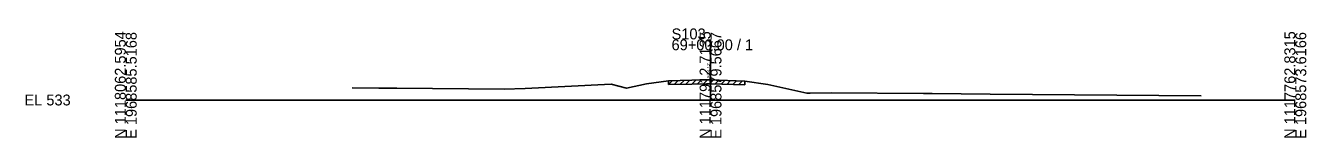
# Model space of a CAD drawing. Extents: x 974 to 1303, y 990 to 14518.
# Drawn here: x 974.3 to 1302.8, y 10990.3 to 11018.4 of the extents above; entities that cross this region are included whole.
import ezdxf

# ---------------------------------------------------------------- set-up
doc = ezdxf.new("R2010")
doc.units = 0
for name, color, linetype in [('Level 10', 7, 'Continuous'), ('Level 60', 7, 'Continuous'), ('Level 61', 7, 'Continuous'), ('Level 63', 7, 'Continuous')]:
    doc.layers.add(name, color=color, linetype=linetype)

msp = doc.modelspace()

# ---------------------------------------------------------------- linework, layer by layer
at = {"layer": 'Level 60'}
for p, q in [((1058.09, 11003.1), (1064.92, 11003.07)), ((1064.92, 11003.07), (1069.53, 11003.06)), ((1069.53, 11003.06), (1097.05, 11002.78)), ((1097.05, 11002.78), (1102.49, 11003)), ((1102.49, 11003), (1124.5, 11004.04)), ((1124.5, 11004.04), (1128.45, 11003.02)), ((1128.45, 11003.02), (1133.58, 11004.2)), ((1133.58, 11004.2), (1139.19, 11004.97)), ((1139.19, 11004.97), (1145.2, 11005.11)), ((1145.2, 11005.11), (1148.99, 11005.2)), ((1148.99, 11005.2), (1150, 11005.17)), ((1150, 11005.17), (1158.78, 11004.87)), ((1158.78, 11004.87), (1164.7, 11004.01)), ((1164.7, 11004.01), (1174.7, 11001.72)), ((1174.7, 11001.72), (1175.58, 11001.74)), ((1175.58, 11001.74), (1180.91, 11001.86)), ((1180.91, 11001.86), (1204.62, 11001.67)), ((1204.62, 11001.67), (1206.81, 11001.66)), ((1206.81, 11001.66), (1221.72, 11001.51)), ((1221.72, 11001.51), (1275.87, 11001.06))]:
    msp.add_line(p, q, dxfattribs=at)
at = {"layer": 'Level 61'}
for p, q in [((1139.19, 11003.97), (1140.21, 11004.99)), ((1139.19, 11003.97), (1139.19, 11004.97)), ((1139.19, 11003.97), (1145.2, 11004.11)), ((1140.69, 11004), (1141.71, 11005.03)), ((1142.19, 11004.04), (1143.21, 11005.06)), ((1143.69, 11004.07), (1144.71, 11005.1)), ((1145.19, 11004.11), (1146.21, 11005.13)), ((1145.2, 11004.11), (1148.99, 11004.2)), ((1146.69, 11004.14), (1147.71, 11005.17)), ((1148.19, 11004.18), (1149.2, 11005.19)), ((1148.99, 11004.2), (1150, 11004.17)), ((1149.69, 11004.18), (1150.66, 11005.14)), ((1150, 11004.17), (1158.78, 11003.87)), ((1151.19, 11004.12), (1152.16, 11005.09)), ((1152.69, 11004.07), (1153.66, 11005.04)), ((1154.19, 11004.02), (1155.16, 11004.99)), ((1155.69, 11003.97), (1156.66, 11004.94)), ((1157.19, 11003.92), (1158.16, 11004.89)), ((1158.78, 11004.87), (1158.78, 11003.87)), ((1158.78, 11003.87), (1158.78, 11003.87))]:
    msp.add_line(p, q, dxfattribs=at)
at = {"layer": 'Level 63'}
for p, q in [((1150, 11000), (1150, 11015.6)), ((1000, 11000), (1150, 11000)), ((1150, 11000), (1300, 11000))]:
    msp.add_line(p, q, dxfattribs=at)

# ---------------------------------------------------------------- texts
at = {"layer": 'Level 10'}
msp.add_text('538.17', height=0.9, rotation=90, dxfattribs=at).set_placement((1149.95, 11005.67))
at = {"layer": 'Level 63'}
for s, p in [('N 1118062.5954', (1000, 10990)), ('E 1968585.5168', (1002.8, 10990)), ('N 1117912.7135', (1150, 10990)), ('E 1968579.5667', (1152.8, 10990)), ('N 1117762.8315', (1300, 10990)), ('E 1968573.6166', (1302.8, 10990))]:
    msp.add_text(s, height=2.8, rotation=90, dxfattribs=at).set_placement(p)
for s, p in [('S103', (1140, 11015.6)), ('69+00.00 / 1', (1140, 11012.8)), ('EL 533', (974, 10998.6))]:
    msp.add_text(s, height=2.8, dxfattribs=at).set_placement(p)

doc.saveas('drawing.dxf')
